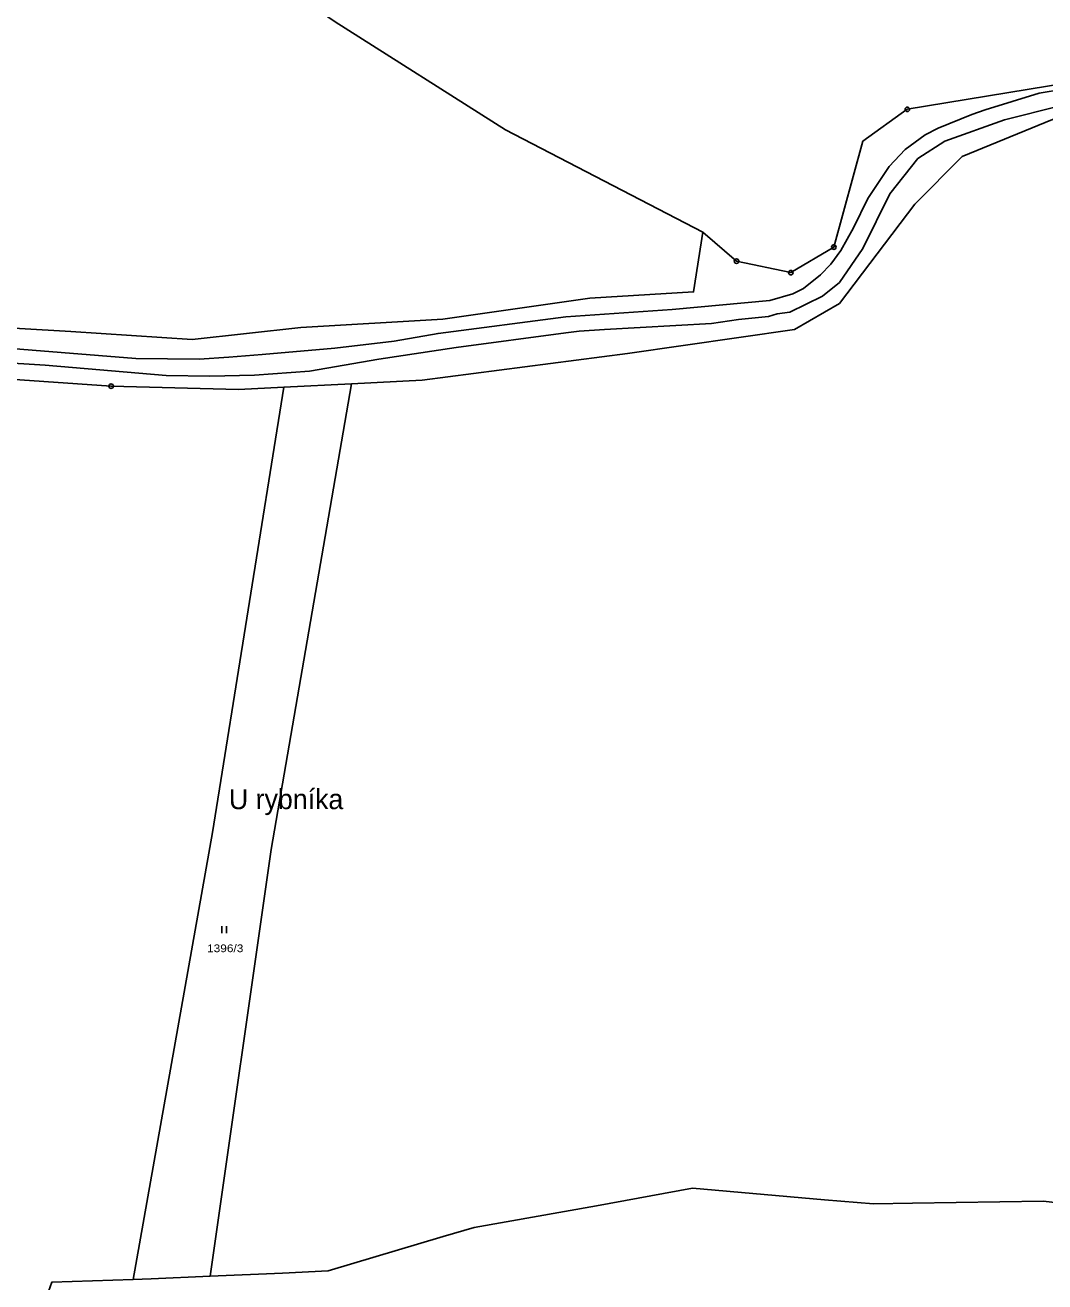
# Model space of a CAD drawing. Extents: x -872229 to -869198, y -1075981 to -1074329.
# Drawn here: x -870264.6 to -870040, y -1075213.2 to -1074936.4 of the extents above; entities that cross this region are included whole.
import ezdxf

# ---------------------------------------------------------------- set-up
doc = ezdxf.new("R2010")
doc.units = 0
doc.header["$LTSCALE"] = 0.68
for name, color, linetype, lineweight in [('1', 7, 'Continuous', 25), ('3', 7, 'Continuous', 25), ('7', 7, 'Continuous', 13), ('8', 7, 'Continuous', 25)]:
    doc.layers.add(name, color=color, linetype=linetype, lineweight=lineweight)
doc.layers.add('2', color=7, linetype='Continuous')

msp = doc.modelspace()

# ---------------------------------------------------------------- linework, layer by layer
at = {"layer": '1'}
msp.add_line((-870207.57, -1075016.13), (-870192.71, -1075015.36), dxfattribs=at)
for points in [[(-870115.36, -1074981.96), (-870158.79, -1074959.47), (-870196.33, -1074935.63), (-870230.5, -1074912.24), (-870256.59, -1074884.78)], [(-869972.29, -1074950.57), (-870021.54, -1074946.89), (-870070.32, -1074954.92), (-870080.13, -1074961.97), (-870086.48, -1074985.27), (-870095.97, -1074990.9), (-870107.93, -1074988.38), (-870115.36, -1074981.96)], [(-870030.59, -1074949.58), (-870041.3, -1074951.38), (-870053.18, -1074955.05), (-870056.07, -1074956.04), (-870063.55, -1074959.11), (-870066.35, -1074960.52), (-870070.78, -1074963.79), (-870074.34, -1074967.55), (-870078.98, -1074974.57), (-870082.13, -1074981.03), (-870084.98, -1074986.04), (-870087.13, -1074989.06), (-870089.45, -1074991.41), (-870093.2, -1074994.42), (-870095.52, -1074995.57), (-870100.55, -1074997.01), (-870122.06, -1074999.05), (-870145.48, -1075000.6), (-870173.64, -1075004.3), (-870183.32, -1075006.02), (-870196.34, -1075007.51), (-870212.39, -1075008.9), (-870219.73, -1075009.49), (-870226.27, -1075009.94), (-870240.2, -1075009.79), (-870279.52, -1075006.66)], [(-870427.04, -1075000.9), (-870260.16, -1075011.3), (-870233.53, -1075013.54), (-870223.87, -1075013.7), (-870214.03, -1075013.5), (-870201.98, -1075012.58), (-870186.67, -1075009.93), (-870169.68, -1075007.4), (-870145.53, -1075004.18), (-870142.58, -1075003.79), (-870136.98, -1075003.46), (-870113.41, -1075002.07), (-870107.51, -1075001.22), (-870100.88, -1075000.55), (-870098.94, -1074999.98), (-870096.16, -1074999.58), (-870088.97, -1074996.08), (-870085.25, -1074993.1), (-870080.09, -1074985.61), (-870074.16, -1074973.56), (-870067.97, -1074965.73), (-870062.07, -1074961.95), (-870048.94, -1074957.25), (-870036.64, -1074954.16)], [(-870192.71, -1075015.36), (-870177.13, -1075014.56), (-870131.91, -1075008.73), (-870095.14, -1075003.44), (-870085.27, -1074997.72), (-870068.68, -1074975.81), (-870058.23, -1074965.32), (-870038.32, -1074957.19), (-870023.13, -1074956.23), (-870015.04, -1074962.59), (-870008.3, -1074975.45), (-870007.09, -1074982.34), (-870000.81, -1074953.44)], [(-870115.36, -1074981.96), (-870117.37, -1074995.15), (-870140.21, -1074996.52), (-870172.56, -1075001.14), (-870203.84, -1075002.96), (-870227.79, -1075005.61), (-870254.49, -1075003.89), (-870314.81, -1075000.31), (-870361.75, -1074998.26), (-870391.78, -1074996.03), (-870411.2, -1074993.72), (-870422.25, -1074993.21), (-870453.27, -1074990.57), (-870470.34, -1074988.35), (-870494.98, -1074984.19), (-870516.43, -1074977.89), (-870524.35, -1074974.36)], [(-870610.36, -1075011.6), (-870588.87, -1075001.44), (-870569.21, -1074993.58), (-870546.64, -1074988.8), (-870536.79, -1074988.15), (-870527.6, -1074989.88), (-870515.91, -1074994.03), (-870492.69, -1074997.19), (-870452.83, -1075001.97), (-870413.18, -1075005.54), (-870363.54, -1075007.87), (-870304.97, -1075011.83), (-870245.64, -1075015.91), (-870217.62, -1075016.65), (-870207.57, -1075016.13)], [(-870240.81, -1075212.65), (-870223.28, -1075114.2), (-870207.57, -1075016.13)], [(-870192.71, -1075015.36), (-870210.36, -1075117.93), (-870223.81, -1075211.98)], [(-870032.43, -1075196.35), (-870040.36, -1075195.42), (-870069.16, -1075195.89), (-870077.74, -1075196.02), (-870088.54, -1075195.1), (-870117.61, -1075192.53), (-870138.77, -1075196.42), (-870165.66, -1075201.23), (-870172.52, -1075203.21), (-870197.84, -1075210.79), (-870207.87, -1075211.32), (-870223.81, -1075211.98)], [(-870240.81, -1075212.65), (-870258.69, -1075213.29), (-870266.01, -1075233.81), (-870266.41, -1075236.59), (-870273.27, -1075250.11), (-870290.79, -1075252.03), (-870312.54, -1075249.92), (-870321.52, -1075248.92), (-870324.09, -1075248.79), (-870341.63, -1075252.94), (-870351.93, -1075255.06), (-870365.6, -1075255.58)], [(-870223.81, -1075211.98), (-870236.81, -1075212.51), (-870240.81, -1075212.65)]]:
    msp.add_lwpolyline(points, dxfattribs=at)
at = {"layer": '3'}
for p, q in [((-870221.241, -1075136.36), (-870221.241, -1075134.86)), ((-870220.24, -1075136.36), (-870220.24, -1075134.86))]:
    msp.add_line(p, q, dxfattribs=at)
at = {"layer": '8'}
for centre, radius in [((-870070.32, -1074954.9199), 0.5), ((-870070.32, -1074954.9199), 0.0303), ((-870086.48, -1074985.2699), 0.5), ((-870086.48, -1074985.2699), 0.0303), ((-870107.93, -1074988.3799), 0.5), ((-870107.93, -1074988.3799), 0.0303), ((-870095.97, -1074990.8999), 0.5), ((-870095.97, -1074990.8999), 0.0303), ((-870245.64, -1075015.9099), 0.5), ((-870245.64, -1075015.9099), 0.0303)]:
    msp.add_circle(centre, radius, dxfattribs=at)

# ---------------------------------------------------------------- texts
at = {"layer": '2', "width": 1.15}
msp.add_text('1396/3', height=1.7, dxfattribs=at).set_placement((-870224.51, -1075140.58))
at = {"layer": '7'}
msp.add_text('U rybníka', height=4.4, dxfattribs=at).set_placement((-870219.69, -1075109.08))

doc.saveas('drawing.dxf')
